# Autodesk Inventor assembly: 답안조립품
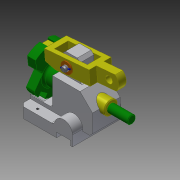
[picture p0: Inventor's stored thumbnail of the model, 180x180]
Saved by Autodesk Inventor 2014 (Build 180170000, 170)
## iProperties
Created: 2016-11
Part Number: 답안조립품
Document SubType Name: Assembly
Designer: USER
Author: USER
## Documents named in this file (8)
- C:\Users\USER\Desktop\461107V1022\답안조립품.iam
- C:\Users\USER\Desktop\461107V1022\본체.ipt
- C:\Users\USER\Desktop\461107V1022\부시.ipt
- C:\Users\USER\Desktop\461107V1022\분할대.ipt
- C:\Users\USER\Desktop\461107V1022\분할축.ipt
- C:\Users\USER\Desktop\461107V1022\와셔.ipt
- C:\Users\USER\Desktop\461107V1022\원통형핀.ipt
- C:\Users\USER\Desktop\461107V1022\클레비스핀.ipt
